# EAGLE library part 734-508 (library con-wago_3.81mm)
Serie 734, Federleiste mit geraden Einlötstiften / Series 734, Female connector with straight solder pins Polzahl / Pole No.: 8 Bemessungsspannung / Rated Voltage: 160 V Nennstrom / Nominal Current: 10 A Lötstiftlänge: / Solder Pin Length: 3.8 mm Farbe / Color: orange / orange Stand: 01.01.2012. Die jeweils aktuellen Daten zu diesem Artikel finden Sie in unserem Produktkatalog, den Sie unter www.wago.com einsehen können. As of: 01/01/2012. Please find the newest data for this article in our product catalogue, which can be viewed under www.wago.com.
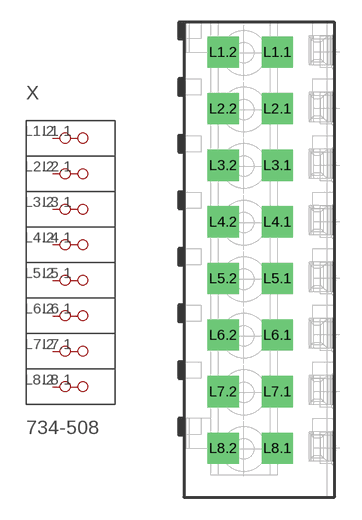
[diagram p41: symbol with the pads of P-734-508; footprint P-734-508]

Designator prefix X

## 734-508  [P-734-508]
L1.1  P1.1
L1.2  P1.2
L2.1  P2.1
L2.2  P2.2
L3.1  P3.1
L3.2  P3.2
L4.1  P4.1
L4.2  P4.2
L5.1  P5.1
L5.2  P5.2
L6.1  P6.1
L6.2  P6.2
L7.1  P7.1
L7.2  P7.2
L8.1  P8.1
L8.2  P8.2

## Footprint P-734-508 (pad centres in mm)
drill 1.4 square: L1.1 1.225,13.98; L1.2 -2.425,13.98; L2.1 1.225,10.17; L2.2 -2.425,10.17; L3.1 1.225,6.36; L3.2 -2.425,6.36; L4.1 1.225,2.55; L4.2 -2.425,2.55; L5.1 1.225,-1.26; L5.2 -2.425,-1.26; L6.1 1.225,-5.07; L6.2 -2.425,-5.07; L7.1 1.225,-8.88; L7.2 -2.425,-8.88; L8.1 1.225,-12.69; L8.2 -2.425,-12.69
